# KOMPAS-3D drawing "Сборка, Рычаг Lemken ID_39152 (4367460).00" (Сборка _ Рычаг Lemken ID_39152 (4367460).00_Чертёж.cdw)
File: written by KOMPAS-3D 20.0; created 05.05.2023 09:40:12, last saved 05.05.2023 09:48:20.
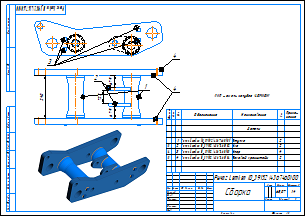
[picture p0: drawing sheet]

Sheet 1: A3, landscape

Document properties: Автор: factory; Масса: 65.0672

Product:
- Part/product: Сборка  | designation Рычаг Lemken ID_39152 (4367460).00
    Масса: 65.0672
    source file: Сборка _ Рычаг Lemken ID_39152 (4367460).00_Чертёж.cdw
  - unknown [Обозначение сварного шва]: (unnamed)
      additional columns: 0; 1; 1; 0.016; 0.016; 0.00123308; 1; Длина, сечение шва и плотность наплавленного материала
  - unknown [Обозначение сварного шва]: (unnamed)
      additional columns: 0; 1; 1; 0.108888; 0.108888; 0.00839172; 1; Длина, сечение шва и плотность наплавленного материала
  - unknown [Обозначение сварного шва]: (unnamed)
      additional columns: 0; 1; 1; 0.054; 0.054; 0.00416163; 1; Длина, сечение шва и плотность наплавленного материала
  - unknown [Обозначение сварного шва]: (unnamed)
      additional columns: 0; 1; 1; 0.305932; 0.305932; 0.0235773; 1; Длина, сечение шва и плотность наплавленного материала
  - Component [detail]: Упор  | designation Рычаг Lemken ID_39152 (4367460).03  | qty 3  | pos. 3  | Материал: Лист$d10х700х5000 ГОСТ 19903-2015;295-09Г2 ГОСТ 19281-2014$ (density 7850 kg/m3); Масса: 0.02669; Форматы листов документа: A4; source file: Упор _ Рычаг Lemken ID_39152 (4367460).03.m3d, Упор _ Рычаг Lemken ID_39152 (4367460).03_Чертёж.cdw
  - Component [detail]: Упор  | designation Рычаг Lemken ID_39152 (4367460).03  | pos. 3  | Материал: Лист$d10х700х5000 ГОСТ 19903-2015;295-09Г2 ГОСТ 19281-2014$ (density 7850 kg/m3); Масса: 0.02669; Форматы листов документа: A4; Зона: 2A; source file: Упор _ Рычаг Lemken ID_39152 (4367460).03.m3d, Упор _ Рычаг Lemken ID_39152 (4367460).03_Чертёж.cdw
  - Component [detail]: Ухо  | designation Рычаг Lemken ID_39152 (4367460).02  | pos. 2  | Материал: Лист$d16х1400х6000 ГОСТ 19903-2015;295-09Г2-ГС ГОСТ 19281-2014$ (density 7850 kg/m3); Масса: 0.803282; Форматы листов документа: A3; source file: Ухо _ Рычаг Lemken ID_39152 (4367460).02.m3d, Ухо _ Рычаг Lemken ID_39152 (4367460).02_Чертёж.cdw
  - Component [detail]: Ухо  | designation Рычаг Lemken ID_39152 (4367460).02  | pos. 2  | Материал: Лист$d16х1400х6000 ГОСТ 19903-2015;295-09Г2-ГС ГОСТ 19281-2014$ (density 7850 kg/m3); Масса: 0.803282; Форматы листов документа: A3; Зона: 2A; source file: Ухо _ Рычаг Lemken ID_39152 (4367460).02.m3d, Ухо _ Рычаг Lemken ID_39152 (4367460).02_Чертёж.cdw
  - Component [detail]: Втулка  | designation Рычаг Lemken ID_39152 (4367460).01  | pos. 1  | Материал: Сталь 40Х  ГОСТ 4543-2016 (density 7850 kg/m3); Масса: 8.48662; Комментарий: Модуль генерации 3D-моделей программы <Валы и механические передачи 2D>; Зона: 2A; source file: Втулка _ Рычаг Lemken ID_39152 (4367460).01.m3d
  - Component [detail]: Втулка  | designation Рычаг Lemken ID_39152 (4367460).01  | pos. 1  | Материал: Сталь 40Х  ГОСТ 4543-2016 (density 7850 kg/m3); Масса: 8.48662; Комментарий: Модуль генерации 3D-моделей программы <Валы и механические передачи 2D>; source file: Втулка _ Рычаг Lemken ID_39152 (4367460).01.m3d
  - Component [detail]: Боковой кронштейн  | designation Рычаг Lemken ID_39152 (4367460).04  | qty 2  | pos. 4  | Материал: Лист$d32х1700х4200 ГОСТ 19903-2015;295-09Г2-ГС ГОСТ 19281-2014$ (density 7850 kg/m3); Масса: 23.1903; Форматы листов документа: A3; Зона: 1A; source file: Боковой кронштейн _ Рычаг Lemken ID_39152 (4367460).04.m3d, Боковой кронштейн _ Рычаг Lemken ID_39152 (4367460).04_Чертёж.cdw

Title block, sheet 1: Наименование: Сборка; designation: Рычаг Lemken ID_39152 (4367460).00; Масса: 65,07; Количество листов документа: 1; Форматы листов документа: A3; stored path: C:\Users\factory\Desktop\Чертежи\Рычаг Lemken ID_39152 (4367460)\Сборка _ Рычаг Lemken ID_39152 (4367460).00_Чертёж.cdw

Views: Проекционный вид 2
Referenced files in C:\Users\factory\Desktop\Чертежи\Рычаг Lemken ID_39152 (4367460)\: Сборка _ Рычаг Lemken ID_39152 (4367460).00_Рис.jpg, Сборка _ Рычаг Lemken ID_39152 (4367460).00.a3d, Упор _ Рычаг Lemken ID_39152 (4367460).03.m3d, Упор _ Рычаг Lemken ID_39152 (4367460).03_Чертёж.cdw, Ухо _ Рычаг Lemken ID_39152 (4367460).02.m3d, Ухо _ Рычаг Lemken ID_39152 (4367460).02_Чертёж.cdw, Втулка _ Рычаг Lemken ID_39152 (4367460).01.m3d, Боковой кронштейн _ Рычаг Lemken ID_39152 (4367460).04.m3d, Боковой кронштейн _ Рычаг Lemken ID_39152 (4367460).04_Чертёж.cdw
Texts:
  Сборка _ Рычаг Lemken ID_39152 (4367460).00_Рис.jpg
  Рычаг Lemken ID_39152 (4367460).03
  Упор
  Рычаг Lemken ID_39152 (4367460).02
  Ухо
  Рычаг Lemken ID_39152 (4367460).01
  Втулка
  Рычаг Lemken ID_39152 (4367460).04
  Боковой кронштейн
  Рычаг Lemken ID_39152 (4367460).04 Боковой кронштейн
  Рычаг Lemken ID_39152 (4367460).01 Втулка
  Рычаг Lemken ID_39152 (4367460).02 Ухо
  Рычаг Lemken ID_39152 (4367460).03 Упор
  Рычаг Lemken ID_39152 (4367460).00 Сборка
Dimensions and other numbers on the sheet: 240; 72,2; 67,9; 4; 1; 2; 3; 1:4; 65,07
